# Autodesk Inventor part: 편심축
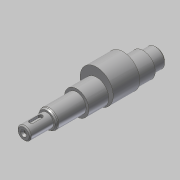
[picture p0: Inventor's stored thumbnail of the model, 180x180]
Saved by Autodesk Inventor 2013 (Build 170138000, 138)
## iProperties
Created: 2019-01
Part Number: 편심축
Material: 강철, 연강
Document SubType Name: Modeling
Designer: mduedu
Density: 7.86 g/cm^3
Mass: 326.79 g
Surface Area: 90.982 cm^2
Volume: 41.5764 cm^3
Author: mduedu
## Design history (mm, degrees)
sketch "스케치1"
  geometry: L1 (0, 0)-(21, 0); L2 (21, 0)-(21, 6); L3 (21, 6)-(0, 6); L4 (0, 6)-(0, 0); L5 (21, 0)-(48, 0); L6 (48, 0)-(48, 8.5); L7 (48, 8.5)-(21, 8.5); L8 (21, 8.5)-(21, 0); L9 (48, 0)-(108, 0); L10 (108, 0)-(108, 11); L11 (108, 11)-(48, 11); L12 (48, 11)-(48, 0); L13 (108, 0)-(120, 0); L14 (120, 0)-(120, 8.5); L15 (120, 8.5)-(108, 8.5); L16 (108, 8.5)-(108, 0)
  constraints: 32 end point, 8 parallel, 4 horizontal, 4 perpendicular
  dimensions: "d0" = 120 distance between parallel lines of L14 L4; "d2" = 12 distance of L14.end L15.end; "d3" = 60 distance of L10.end L11.end; "d4" = 99 distance between parallel lines of L8 L14; "d5" = 12 diameter of L3 L1; "d6" = 17 diameter of L7 L5; "d7" = 17 diameter of L15 L13; "d8" = 22 diameter of L11 L9
revolve "회전1" sketch "스케치1" stored, may be unused: angle "d9" = 90 deg
node "작업 평면1"
sketch "스케치2"
  geometry: C1 r 15 at (0, 4); C2 r 11 at (0, 0) reference; 1 further point
  constraints: 1 centre point, 1 tangent, 1 vertical alignment
  dimensions: "d11" = 4 distance of point (0, 0) C1.centre
extrude "돌출1" join sketch "스케치2" distance "d12" = 24; taper "d13" = 0 deg
node "작업 평면2"
sketch "스케치3" dims "d16" = 12
  geometry: L1 (-4.5, 2)-(3.5, 2); L2 (3.5, 2)-(3.5, -2); L3 (3.5, -2)-(-4.5, -2); L4 (-4.5, -2)-(-4.5, 2); L5 (-10.5, 8.5)-(-10.5, -8.5) reference; 3 further points
  constraints: 8 end point, 2 midpoint, 2 parallel, 2 vertical alignment, 1 horizontal, 1 horizontal alignment, 1 perpendicular, 4 other
  dimensions: "d14" = 4 distance between parallel lines of L3 L1; "d17" = 4 dimension on L5
extrude "돌출2" cut sketch "스케치3" distance "d18" = 2.5; taper "d19" = 0 deg
chamfer "모따기1" distance "d20" = 1.82; stored, may be unused: second distance "d21" = 2, angle "d22" = 30 deg
fillet "모깎기1" dims "d23" = 2
hole "구멍2" diameter "d39" = 3.242; stored, may be unused: countersink angle "d43" = 60 deg, drill point angle "d45" = 118 deg; dims "d37" = 10, "d38" = 10, "d40" = 8, "d41" = 5.51, "d42" = 2, "d44" = 10
sketch "스케치5"
  geometry: L1 (0, 0)-(2, 0); L2 (2, 0)-(2, 1.621); L3 (0, 2.776)-(0, 0); L4 (0, 2.776)-(2, 1.621); L5 (10, 1.621)-(0, 1.621) reference
  constraints: 8 end point, 1 horizontal, 1 parallel, 1 perpendicular, 1 point on line
  dimensions: "d46" = 2 distance between parallel lines of L2 L3; "d48" = 30 deg angle of L4 L1
revolve "회전2" sketch "스케치5" stored, may be unused: angle "d50" = 90 deg
chamfer "모따기2" distance "d25" = 1; stored, may be unused: second distance "d26" = 2, angle "d27" = 30 deg
node "솔리드1"
